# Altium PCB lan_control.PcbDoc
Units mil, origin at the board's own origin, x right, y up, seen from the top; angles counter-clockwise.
Board outline 3947.03 x 3354.83 mil, 2 copper layers (Top Layer, Bottom Layer); 54 components, 48 nets, 205 pads, 217 vias.
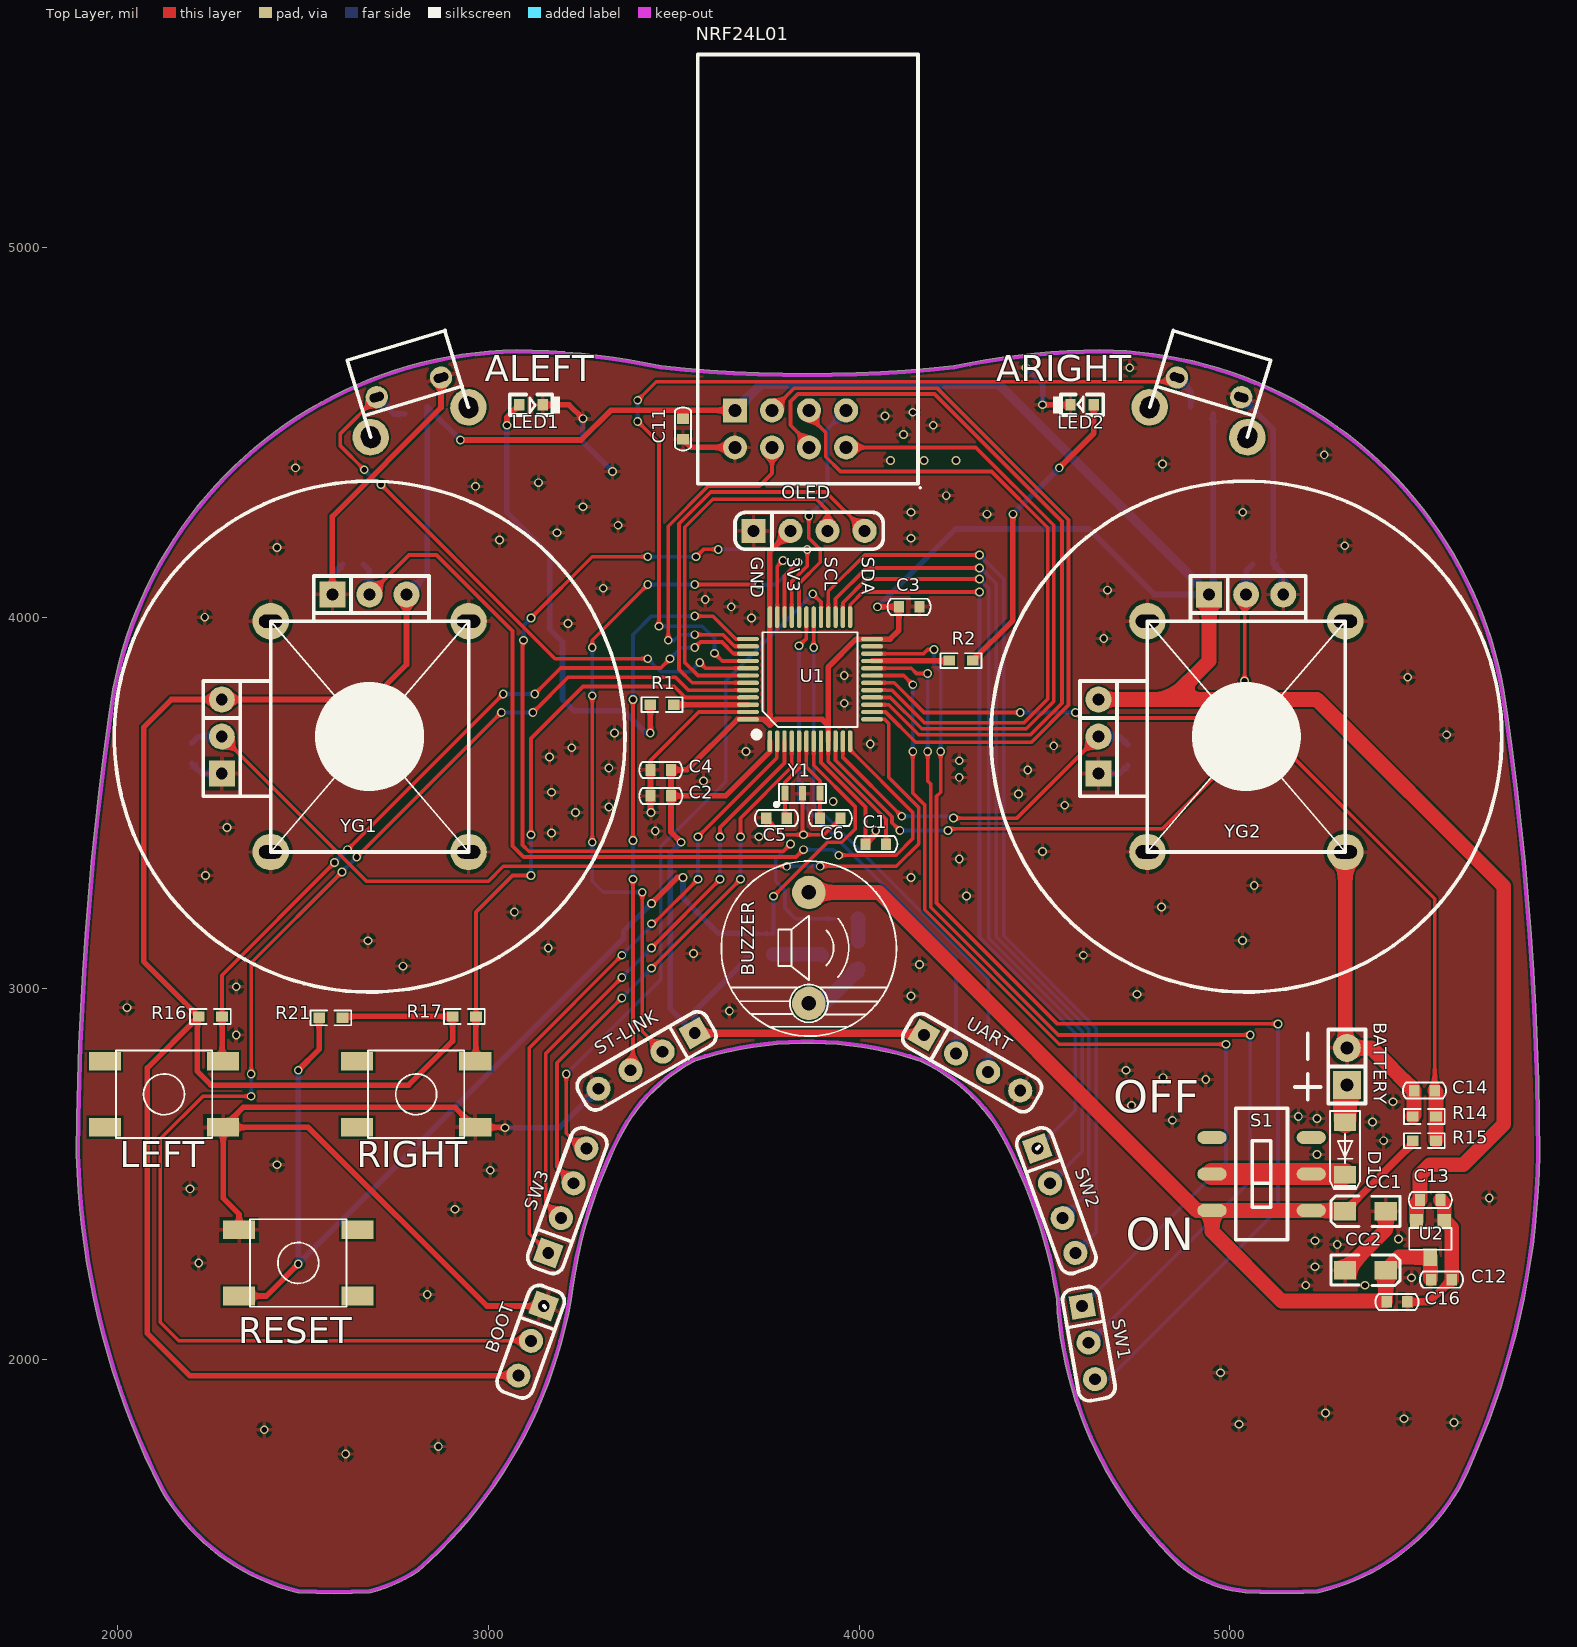
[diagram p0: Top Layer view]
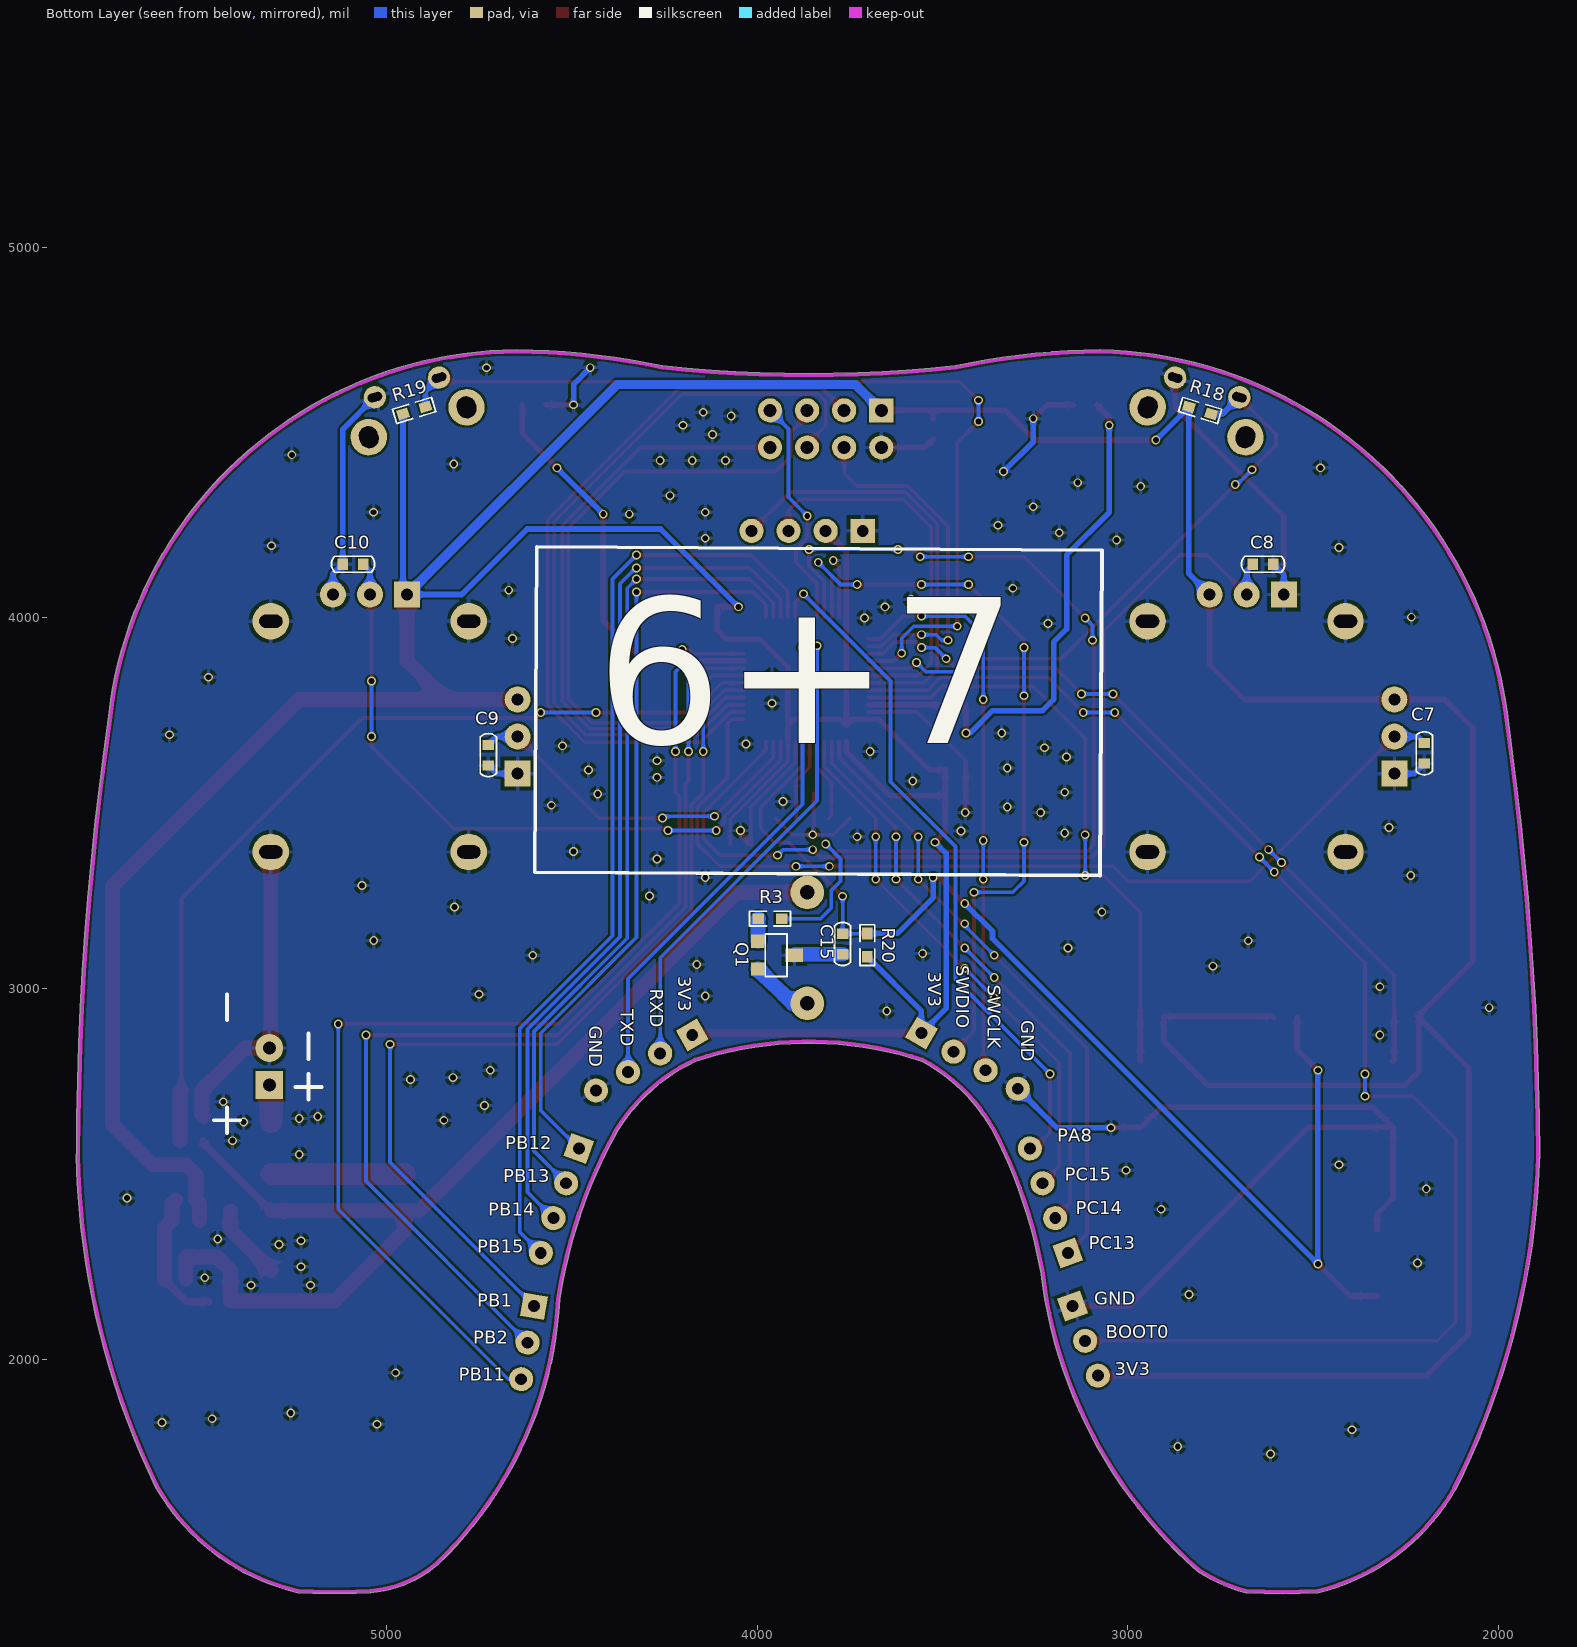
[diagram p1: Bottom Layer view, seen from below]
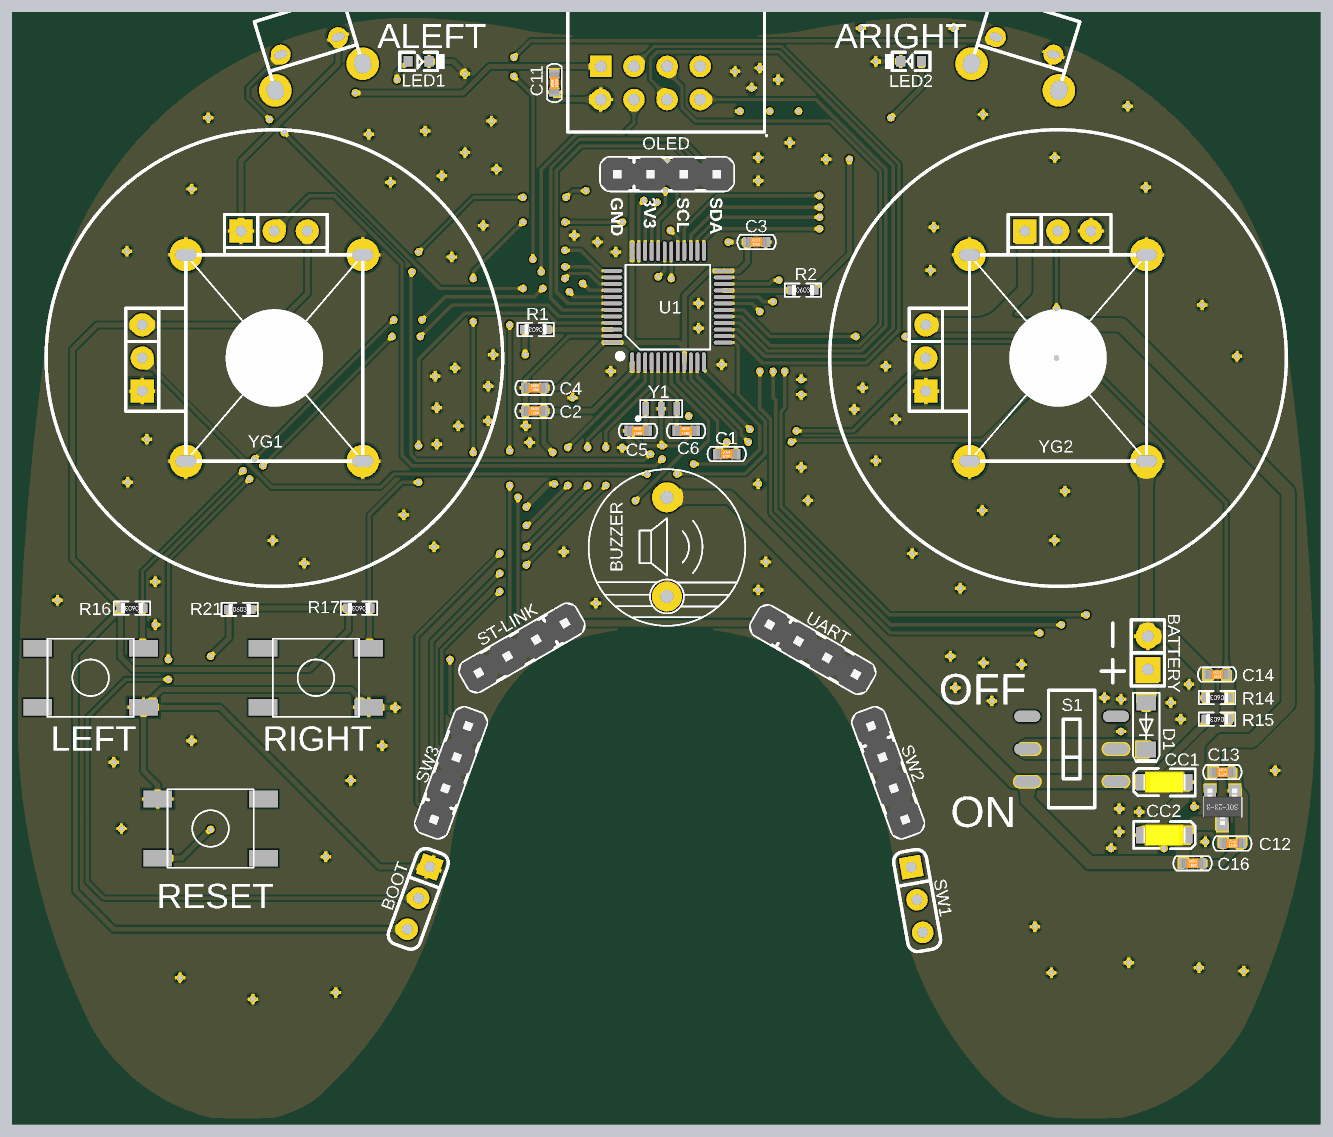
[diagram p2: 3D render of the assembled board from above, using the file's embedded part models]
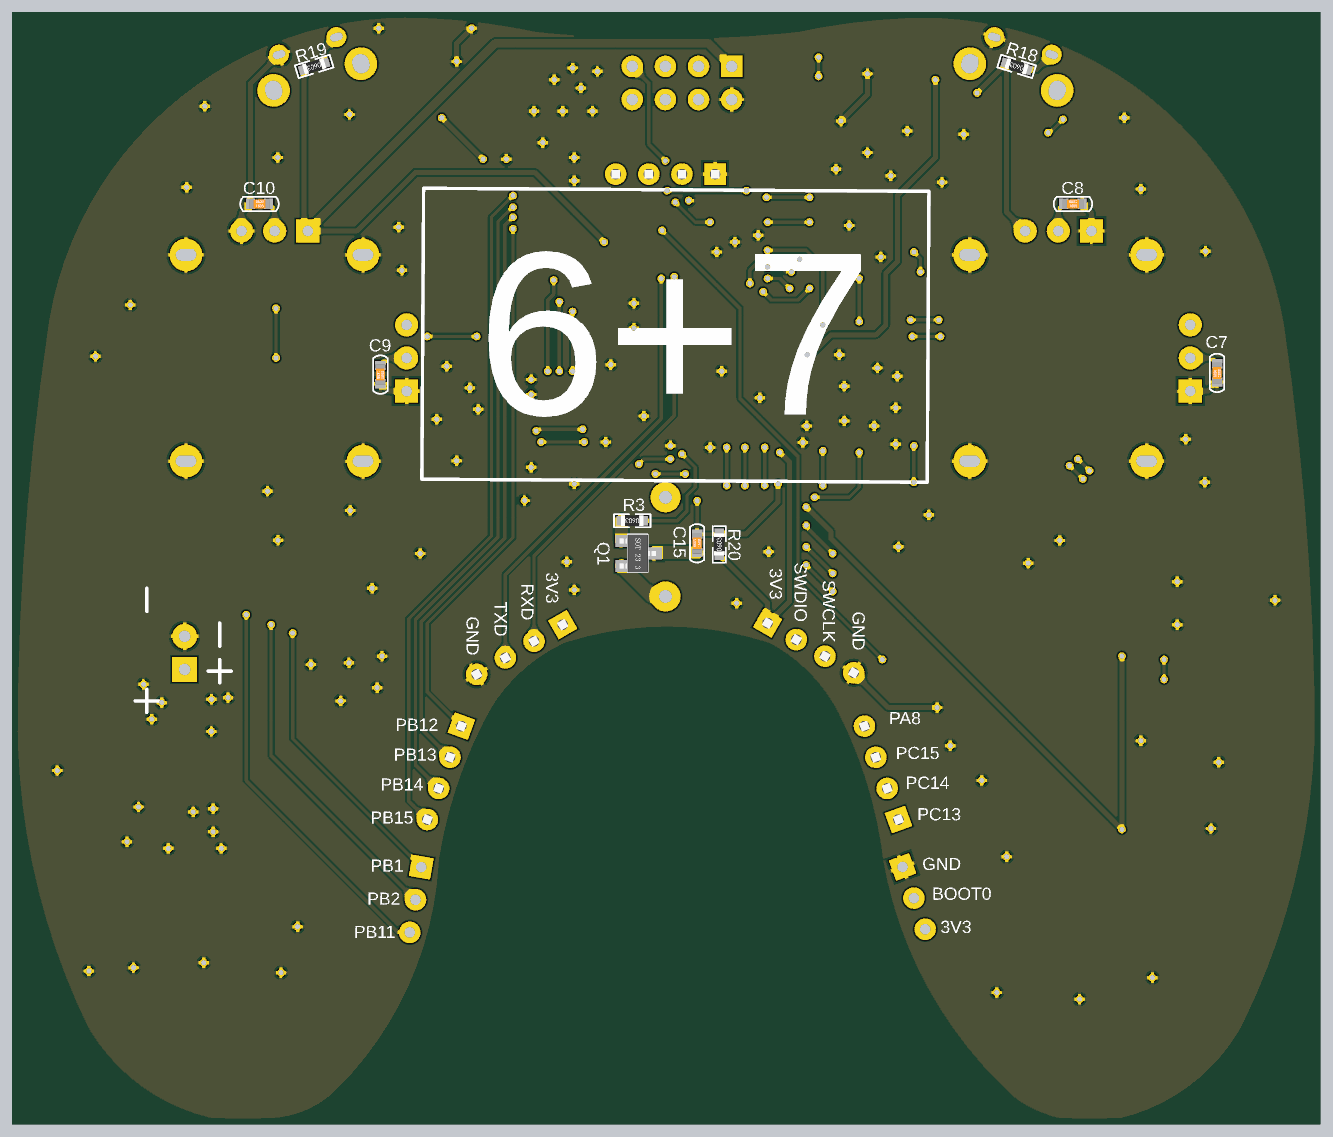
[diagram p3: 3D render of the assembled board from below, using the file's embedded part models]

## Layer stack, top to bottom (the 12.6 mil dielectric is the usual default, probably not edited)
Top Solder: solder mask 0.4, Solder Resist, Dk 3.5
Top Layer: signal copper 1.4
Dielectric 1: dielectric 12.6, FR-4, Dk 4.8
Bottom Layer: signal copper 1.4
Bottom Solder: solder mask 0.4, Solder Resist, Dk 3.5

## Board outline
2486.67,1370.8 ccw(c2487.17,1375.79) 2486.93,1370.78 ccw(c2583.63,3341.93) 2680.33,1370.78 ccw(c2680.08,1375.79) 2680.44,1370.78 ccw(c2680.08,1375.79) 2681.3,1370.92 ccw(c2587.07,1760.86) 2812.02,1428.7 ccw(c2587.07,1760.86) 2812.05,1428.72 2812.02,1428.7 ccw(c2809.24,1432.87) 2812.55,1429.11 ccw(c1973.33,2381.46) 3223.63,2162.32 ccw(c3218.69,2163.19) 3223.67,2162.58 cw(c4538.77,2003.24) 3357.01,2601.84 ccw(c3352.55,2604.13) 3357.01,2601.84 cw(c4538.77,2003.24) 3357.02,2601.87 ccw(c3352.55,2604.13) 3357.02,2601.87 cw(c3782.54,2383.23) 3555.42,2804.29 cw(c3860.42,1873.76) 4165.51,2804.26 cw(c3952.67,2353.1) 4375.79,2617.33 cw(c3176.19,1949.24) 4532.59,2162.67 ccw(c5594.98,2216.85) 4860.9,1446.96 ccw(c4864.36,1450.59) 4861.08,1446.8 ccw(c5067.76,1685.5) 5042.18,1370.79 5042.34,1370.78 ccw(c5140.12,3341.87) 5237.91,1370.78 ccw(c5237.66,1375.79) 5238.21,1370.8 ccw(c5237.66,1375.79) 5238.81,1370.91 ccw(c5105.6,1951.38) 5621.76,1654.26 ccw(c5617.41,1656.76) 5621.92,1654.57 ccw(c3705.18,2585.84) 5835.92,2552.78 ccw(c5830.91,2552.86) 5835.92,2552.86 ccw(c5830.91,2552.86) 5835.91,2553.22 ccw(c-2681.94,2522.43) 5749.27,3734.6 ccw(c4643.92,3611) 4649.84,4723.23 ccw(c4649.81,4718.22) 4649.81,4723.23 ccw(c4649.81,4718.22) 4649.77,4723.23 ccw(c4664.52,2756.14) 4255.32,4680.26 cw(c3859.14,8433.86) 3465.79,4679.96 ccw(c3053.83,2745.84) 3075.06,4723.23 ccw(c3075.01,4718.22) 3075.01,4723.23 ccw(c3075.01,4718.22) 3074.92,4723.23 ccw(c3094.76,3595.59) 1975.55,3734.67 ccw(c3094.76,3595.59) 1975.54,3734.58 1975.55,3734.67 ccw(c10675.5,2502.64) 1888.89,2552.89 ccw(c1893.91,2552.86) 1888.9,2552.76 ccw(c1893.91,2552.86) 1888.9,2552.73 ccw(c4019.2,2607.34) 2115.78,1649.12 ccw(c2120.26,1651.38) 2115.91,1648.88 ccw(c2624.96,1941.26) 2485.94,1370.92 ccw(c2624.96,1941.26) 2485.99,1370.91 2485.94,1370.92 ccw(c2487.17,1375.79)

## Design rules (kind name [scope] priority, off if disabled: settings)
Clearance [All] p1: gap=6 ignorepadtopadclearanceinfootprint=FALSE
PolygonConnect [All] p1: connectstyle=Relief reliefconductorwidth=10 reliefentries=4 polygonreliefangle="90 Angle" airgapwidth=10
RoutingVias [All] p1: holewidth=28 width=50 viastyle="Through Hole" minholewidth=28 minwidth=50 maxholewidth=28 maxwidth=50
SolderMaskExpansion [All] p1: expansion=4
Width [All] p1: maxlimit=200 minlimit=10 preferedwidth=40 toplayer_prefwidth=20 minimp=50.000000 maximp=50.000000 favimp=50.000000
30 further rules are at their usual default settings.

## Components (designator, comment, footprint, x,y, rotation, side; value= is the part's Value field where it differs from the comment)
ALEFT "左肩键" FWAL 2800,4575 r197 top
ARIGHT "右肩键" FWAL 4930,4575 r163 top
BATTERY "DC4.2V" SIP2 5315.86,2740 r90 top
BOOT "CON3" SIP3 3149.06,2143.78 r250 top
BUZZER "Bell" 蜂鸣器BUZZER-D12 3865,3110 r0 top
C1 "100NF" C_0603 4045,3390 r180 top
C2 "100NF" C_0603 3465,3520 r0 top
C3 "100NF" C_0603 4135,4030 r180 top
C4 "100NF" C_0603 3465,3590 r0 top
C5 "22PF" C_0603 3777.34,3460 r180 top
C6 "22PF" C_0603 3922.34,3460 r180 top
C7 "100NF" C_0603 2200,3635 r270 bottom
C8 "100NF" C_0603 2635,4145 r180 bottom
C9 "100NF" C_0603 4725,3630 r270 bottom
C10 "100NF" C_0603 5090,4145 r180 bottom
C11 "100NF" C_0603 3525,4510 r270 top
C12 "100NF" C_0603 5570.86,2215 r0 top
C13 "100NF" C_0603 5540.86,2430 r0 top
C14 "100NF" C_0603 5525,2725 r0 top
C15 "100NF" C_0603 3769.23,3120.68 r90 bottom
C16 "100NF" C_0603 5450.86,2155 r0 top
CC1 "10uF" C_1206 5365.86,2400 r0 top
CC2 "10uF" C_1206 5365.86,2240 r180 top
D1 "IN4007" SOD-123 5310.86,2640 r270 top
LED1 "R_LED" LED0603 3115,4575 r270 top
LED2 "B_LED" LED0603 4601.5,4575 r90 top
LEFT "左键" KEYSW-6X6 2125,2715 r180 top
NRF24L01 "HEADER 4X2" 24L01 3815,4510 r270 top
OLED "OLED" SIP4 3715.23,4234.93 r0 top
Q1 "2TY" SOT23-213 3948.32,3090 r270 bottom
R1 "103" R0603 3468.26,3765.94 r180 top value=1K
R2 "103" R0603 4275,3885 r0 top value=1K
R3 "103" R0603 3965,3188.76 r0 bottom value=10K
R14 "103" R0603 5525,2655 r180 top value=10K
R15 "103" R0603 5525,2590 r180 top value=10K
R16 "103" R0603 2250,2925 r180 top value=10K
R17 "103" R0603 2935,2925 r180 top value=10K
R18 "103" R0603 2805,4560 r17 bottom value=10K
R19 "103" R0603 4925,4560 r343 bottom value=10K
R20 "103" R0603 3702.58,3117.5 r90 bottom value=10K
R21 "103" R0603 2575,2921.5 r0 top value=10K
RESET "RESET键" KEYSW-6X6 2487.17,2260 r0 top
RIGHT "右键" KEYSW-6X6 2805,2715 r180 top
S1 "MSS22D18" MSS22D18 5085.86,2500 r90 top
ST-LINK "ST-LINK" SIP4 3556.37,2879.95 r210 top
SW1 "CON3" SIP3 4601.77,2143.25 r280 top
SW2 "CON4" SIP4 4480.81,2568.73 r290 top
SW3 "CON4" SIP4 3161.74,2287.25 r70 top
U1 "STM32F103C8T6_LQFP48" LQFP48_STM32 3759.41,3667.52 r90 top
U2 "XC6206" SOT23-PIN132 5540.86,2325 r180 top
UART "UART" SIP4 4175,2875 r330 top
Y1 "8MHZ" Y3213 3847.34,3526.87 r0 top
YG1 "5K" GY 2680,3680 r0 top
YG2 "5K" GY 5045,3680 r0 top

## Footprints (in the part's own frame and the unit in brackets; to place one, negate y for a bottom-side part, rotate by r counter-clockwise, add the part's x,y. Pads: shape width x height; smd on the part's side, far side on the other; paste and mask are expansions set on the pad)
24L01 [mil]
  round 65 hole 35: 1(50,-150) 3(50,-50) 4(-50,-50) 5(50,50) 6(-50,50) 7(50,150) 8(-50,150)
  rect 65x65 hole 35: 2(-50,-150)
  silkscreen extent -1010,-250 159,350
C_0603 [mm]
  rect 0.7x0.8 smd: 1(-0.703,0) 2(0.703,0)
  silkscreen extent -1.48,-0.55 1.48,0.55, body extent -0.8,-0.4 0.8,0.4, height 0.8
C_1206 [mil]
  rect 60x50 smd: 1(-55,0) 2(55,0)
  silkscreen extent -93,-42 93,41, body extent -63,-31 63,31, height 63
FWAL [mm]
  round 2.5 hole 1.3 slot 1.5 at 90 deg: 1(3.5,1.25) 2(-3.5,1.25)
  round 1.524 hole 0.6 slot 1 at 0 deg: 3(2.3,-1.25) 4(-2.3,-1.25)
  silkscreen extent -3.5,-4.25 3.5,1.25
GY [mil]
  rect 70x70 hole 32: 1(-399.12,-100) 4(-100.85,383.25)
  round 70 hole 32: 2(-399.12,0) 3(-399.12,100) 5(-0.85,383.25) 6(99.15,383.25)
  round 98.43 hole 35.43 slot 62.99 at 0 deg: 7(-267.31,311.21) 8(266.69,311.21) 9(266.69,-311.21) 10(-267.31,-311.21)
  silkscreen extent -689,-689 689,689
KEYSW-6X6 [mm]
  rect 2.2x1.27 smd: 1(-4.051,-2.263) 2(-4.051,2.263) 3(4.051,-2.263) 4(4.051,2.263)
  silkscreen extent -3.3,-3 3.3,3
LED0603 [mm]
  rect 0.8x0.7 smd: 1(0,-0.8) 2(0,0.8)
  silkscreen extent -0.7,-1.45 0.7,1.99
LQFP48_STM32 [mm]
  oval 1.5x0.3 smd: 1(0,0) 2(0,-0.5) 3(0,-1) 4(0,-1.5) 5(0,-2) 6(0,-2.5) 7(0,-3) 8(0,-3.5) 9(0,-4) 10(0,-4.5) 11(0,-5) 12(0,-5.5) 25(8.5,-5.5) 26(8.5,-5) 27(8.5,-4.5) 28(8.5,-4) 29(8.5,-3.5) 30(8.5,-3) 31(8.5,-2.5) 32(8.5,-2) 33(8.5,-1.5) 34(8.5,-1) 35(8.5,-0.5) 36(8.5,0)
  oval 0.3x1.5 smd: 13(1.5,-7) 14(2,-7) 15(2.5,-7) 16(3,-7) 17(3.5,-7) 18(4,-7) 19(4.5,-7) 20(5,-7) 21(5.5,-7) 22(6,-7) 23(6.5,-7) 24(7,-7) 37(7,1.5) 38(6.5,1.5) 39(6,1.5) 40(5.5,1.5) 41(5,1.5) 42(4.5,1.5) 43(4,1.5) 44(3.5,1.5) 45(3,1.5) 46(2.5,1.5) 47(2,1.5) 48(1.5,1.5)
  silkscreen extent 0.3,-5.99 7.47,1.07
MSS22D18 [mm]
  oval 0.889x2 smd: 1(-2.5,-3.4) 2(0,-3.4) 3(2.5,-3.4) 4(2.5,3.4) 5(0,3.4) 6(-2.5,3.4)
  silkscreen extent -4.5,-1.77 4.5,1.77, body extent -4.44,-1.78 4.44,1.78, height 3
R0603 [mm]
  rect 0.8x0.7 smd: 1(-0.8,0) 2(0.8,0)
  silkscreen extent -1.4,-0.51 1.4,0.51, body extent -0.85,-0.41 0.85,0.39, height 0.56
SIP2 [mil]
  rect 75x75 hole 35: 1(0,0)
  round 75 hole 35: 2(100,0)
  silkscreen extent -50,-50 150,50
SIP3 [mil]
  rect 65x65 hole 32: 1(-0.23,0.07)
  round 65 hole 32: 2(99.77,0.07) 3(199.77,0.07)
  silkscreen extent -50,-50 255,50, body extent -50,-50 250,50, height 10
SIP4 [mil]
  rect 65x65 hole 32: 1(-0.23,0.07)
  round 65 hole 32: 2(99.77,0.07) 3(199.77,0.07) 4(299.77,0.07)
  silkscreen extent -50,-50 350,50, body extent -50,-50 350,50, height 336
SOD-123 [mm]
  rect 1.2x1.5 smd: 1(0,0) 2(3.6,0)
  silkscreen extent -0.76,-1.02 4.57,1.02
SOT23-213 [mil]
  rect 36x47.24 smd: 1(-0.36,48.99)
  rect 36x36 smd: 2(-37.86,-49.43) 3(37.14,-49.43)
  silkscreen extent -57,-30 57,29, body extent -57,-55 57,55, height 47
SOT23-PIN132 [mil]
  rect 36x36 smd: 1(-37.86,-49.43) 2(37.14,-49.43)
  rect 36x47.24 smd: 3(-0.36,48.99)
  silkscreen extent -57,-30 57,29, body extent -57,-55 57,55, height 47
Y3213 [mm]
  rect 0.5x1 smd: 1(-1.2,0) 2(0,0) 3(1.2,0)
  silkscreen extent -1.9,-0.89 1.6,0.65, body extent -1.52,-0.64 1.52,0.64, height 0.8
蜂鸣器BUZZER-D12 [mm]
  round 2.3 hole 1: 1(-0.013,3.8) 2(-0.013,-3.8)
  silkscreen extent -6.01,-6.05 5.99,5.95

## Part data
ALEFT ARIGHT: library part SW-PB
BATTERY: library part CON2, "Connector"
BUZZER: "Electrical Bell"
C1 C2 C3 C4 C5 C6 C7 C8 C9 C10 C11 C12 C13 C14 C15 C16: library part CAP, "Capacitor"
CC1 CC2: library part "CAPACITOR POL", "Capacitor"
D1: library part DIODE, "Diode"
LED1 LED2: library part LED
LEFT RESET RIGHT: library part SW
OLED ST-LINK UART: library part CON4, "Connector"
Q1: library part PNP, "PNP Bipolar Transistor"
R1 R2 R3 R14 R15 R16 R17 R18 R19 R20 R21: library part Res2, "Resistor"
S1: library part SW2X3
SW2 SW3: "Connector"
U1: library part STM32_LQFP48
U2: library part LM317, "3-Terminal Adjustable Positive Voltage Regulator"
Y1: library part Y
YG1 YG2: library part YG

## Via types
v1: diameter 23.62, hole 15.75, Top Layer to Bottom Layer, 217 vias

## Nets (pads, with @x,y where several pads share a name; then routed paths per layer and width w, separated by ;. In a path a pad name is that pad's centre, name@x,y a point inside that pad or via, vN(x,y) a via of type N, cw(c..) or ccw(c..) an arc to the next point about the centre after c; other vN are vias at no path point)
3V3: BOOT.3 C1.1 C2.2 C3.2 C4.2 C11.1 C13.1 NRF24L01.2 OLED.2 R16.2 R17.2 R18.2 R19.2 R20.1 R21.2 ST-LINK.1 U1.1 U1.9 U1.24 U1.36 U1.48 U2.2 UART.1 YG1.3 YG1.6 YG2.3 YG2.4 | length 16193.5
  Top Layer w10: U1.9 3916.89,3613.02 4072.67,3457.24 C1.1 ; UART.1@4170.01,2880 UART.1
  Top Layer w15: R21.2 2610,2925 R17.2 2903.5,2858.5 2785,2740 2251.73,2740 2215,2776.73 R16.2@2215,2921.5 ; YG1.6 2779.15,3874.15 2685,3780 YG1.3 2145,3780 2070,3705 2070,3073.5 R16.2 R16.2@2215,2921.5 ; v1(2924.33,4480) 3250,4480 3330,4560 3535,4560 ; BOOT.3 2193.97,1956.03 2080,2070 2080,2786.5 R16.2@2215,2921.5 ; v1(3520,3395) 3492.67,3422.33 C2.2 ; C11.1 3525,4550 3535,4560 ; NRF24L01.2 3535,4560 ; U1.1 3759.41,3639.41 3640,3520 C2.2 ; OLED.2 3759.41,4179.41 U1.36 3759.41,3710 ; 3916.61,3710.38 3900.41,3726.57 3775.98,3726.57 3759.41,3710 ; U1.9 3916.89,3867.58 3992.14,3942.83 4034.72,3942.83 U1.24 4083.5,3943.11 4107.33,3966.94 C3.2 v1(4050,4030) ; C2.2 C4.2 3535,3590 3671.57,3726.57 U1.48 3742.83,3726.57 3759.41,3710
  Top Layer w20: ST-LINK.1 UART.1@4170.01,2880
  Top Layer w40: YG2.3 4840,3780 ; YG2.4 4944.15,3884.15 4840,3780 ; U2.2 5503.71,2420.53 C13.1 5513.19,2498.27 5539.92,2525 5630,2525 5739.25,2634.25 5739.25,3276.07 5235.31,3780 4840,3780
  Bottom Layer w15: YG1.6 2835.12,4119.23 R18.2 v1(2924.33,4480) ; v1(3520,3395) 3490,3365 3490,2946.6 ST-LINK.1 3556.6,2940.03 R20.1 ; v1(4050,4030) 4260,4240 4620,4240 4796.75,4063.25 YG2.4 4955.12,4074.23 R19.2
  Bottom Layer w25: NRF24L01.2 3735,4630 4377.4,4630 YG2.4
ADC0: C10.2 U1.10 YG2.5 | length 1837.7
  Top Layer w10: U1.10 3936.57,3615.97 4088.67,3463.87 4088.67,3447.89 v1(4110,3426.56) ; v1(4240,3426.56) 4245,3431.56 4818.26,3431.56 5040,3653.29 v1(5040,3680) ; v1(5040,3830) 5040,4059.11 YG2.5
  Bottom Layer w10: v1(4110,3426.56) v1(4240,3426.56) ; v1(5040,3680) v1(5040,3830)
  Bottom Layer w15: YG2.5 5044.15,4126.82 C10.2
ADC1: C9.1 U1.11 YG2.2 | length 980.6
  Top Layer w10: U1.11 3956.26,3623.74 v1(4115,3465) ; v1(4255,3460.09) 4425.96,3460.09 YG2.2
  Bottom Layer w10: v1(4115,3465) 4250.09,3465 v1(4255,3460.09)
  Bottom Layer w15: YG2.2 4702.67,3680 C9.1
ADC2: C8.1 U1.12 YG1.5 | length 2641.7
  Top Layer w10: YG1.5 2785.89,4170 2860,4170 3065,3965 3065,3385 3095,3355 3830,3355 v1(3850,3375) ; v1(3945,3360) 4100,3360 4145,3405 4145,3475.39 3975.94,3644.45 U1.12
  Bottom Layer w10: v1(3850,3375) 3930,3375 v1(3945,3360)
  Bottom Layer w15: C8.1 2679.15,4128.52 YG1.5
ADC3: C7.1 U1.13 YG1.2 | length 2579.1
  Top Layer w10: YG1.2 2670.88,3290 3000,3290 3040,3330 v1(3805,3330) ; v1(3895,3330) 4100.39,3330 4161,3390.61 4161,3489 4080,3570 4080,3715 4068.43,3726.57 U1.13
  Bottom Layer w10: v1(3805,3330) v1(3895,3330)
  Bottom Layer w15: C7.1 2217.33,3680 YG1.2
ALEFT_KEY: ALEFT.3 R18.1 U1.41 | length 1635.9
  Top Layer w10: v1(2665,4400) 2600,4465 2600,4496.57 ALEFT.3 ; v1(2710,4360) 3180,3890 v1(3430,3890) ; v1(3570,3880) 3585.63,3864.37 U1.41
  Bottom Layer w10: v1(2665,4400) 2705,4360 v1(2710,4360) ; v1(3430,3890) 3465,3855 3545,3855 v1(3570,3880)
  Bottom Layer w15: ALEFT.3 2743.81,4550.79 R18.1
ARIGHT_KEY: ARIGHT.3 R19.1 U1.40 | length 2511.1
  Top Layer w10: v1(3402.67,4530) 3460,4472.67 v1(3460,3977.81) ; v1(3402.67,4587.33) 3452.83,4637.49 4846.75,4637.49 ARIGHT.3 ; v1(3610,3905) 3630.95,3884.05 U1.40
  Bottom Layer w10: v1(3402.67,4530) v1(3402.67,4587.33) ; v1(3460,3977.81) 3577.19,3977.81 3610,3945 v1(3610,3905)
  Bottom Layer w15: ARIGHT.3 4894.88,4611.45 R19.1
B_LED: R2.1 U1.21 | length 208.9
  Top Layer w15: U1.21 4242.56,3884.05 R2.1
BAT_DET: C14.2 R14.1 R15.1 U1.18 | length 2412.9
  Top Layer w10: U1.18 4095,3825 4175,3745 v1(4434.65,3745) ; v1(4583.4,3745) 4598.4,3730 5065,3730 5552.67,3242.33 C14.2
  Top Layer w40: C14.2 5556.5,2721.17 R14.1 R15.1
  Bottom Layer w10: v1(4434.65,3745) v1(4583.4,3745)
BOOT0: BOOT.2 U1.44 | length 3842
  Top Layer w10: v1(2360,2710) 2230,2710 2115,2595 2115,2100 2165,2050 BOOT.2 ; v1(2360,2770) 2360,3070 v1(2605,3315) ; v1(2645,3355) v1(3035,3745) ; v1(3120,3745) 3215,3840 3505,3840 3539.68,3805.32 U1.44
  Bottom Layer w10: v1(2360,2710) v1(2360,2770) ; v1(2605,3315) v1(2645,3355) ; v1(3035,3745) v1(3120,3745)
BUZZER: R3.1 U1.33 | length 2725.8
  Top Layer w10: v1(3095,3940) 3092.19,3937.19 3092.19,3387.81 3109,3371 3796,3371 v1(3815,3390) ; v1(3115,4000) 3280,4165 v1(3430,4165) ; v1(3560,4165) 3580,4185 v1(3620,4185) ; U1.33 3818.46,4098.46 3860,4140 v1(3860,4185)
  Bottom Layer w10: v1(3095,3940) 3095,3980 v1(3115,4000) ; v1(3430,4165) v1(3560,4165) ; v1(3620,4185) v1(3860,4185) ; v1(3815,3390) 3775,3350 3775,3290 3800,3265 3800,3217.5 3828.74,3188.76 R3.1
CE: NRF24L01.3 U1.38 | length 951.2
  Top Layer w10: v1(3485,3940) 3485,4247.63 3593.37,4356 3731,4356 3765,4390 NRF24L01.3 ; v1(3556.6,3955) 3632.63,3955 3664.2,3923.43 U1.38
  Bottom Layer w10: v1(3485,3940) 3501.57,3940 3516.57,3955 v1(3556.6,3955)
CSN: NRF24L01.4 U1.14 | length 2077
  Top Layer w10: NRF24L01.4 3825,4620 4210,4620 4565,4265 4565,3765 4465,3665 4152.63,3665 4071.37,3746.26 U1.14
GND: ALEFT.4 ARIGHT.4 BATTERY.2 BOOT.1 C1.2 C2.1 C3.1 C4.1 C5.2 C6.1 C7.2 C8.2 C9.2 C10.1 C11.2 C12.2 C13.2 C14.1 C15.1 C16.2 CC1.2 CC2.2 LED1.2 LED2.2 LEFT.2 NRF24L01.1 OLED.1 Q1.1 R14.2 RESET.2 RIGHT.2 ST-LINK.4 U1.8 U1.23 U1.35 U1.47 U2.1 UART.4 Y1.2 YG1.1 YG1.4 YG1.7 YG1.8 YG1.9 YG1.10 YG2.1 YG2.6 YG2.7 YG2.8 YG2.9 YG2.10 | length 7550.3
  Top Layer w10: C4.1 3437.33,3615.83 3567.76,3746.26 U1.47 ; C5.2 3794.67,3415 v1(3849.84,3415) ; U1.35 3779.09,4139.42 v1(3794.67,4155) ; Y1.2 3847.34,3417.5 v1(3849.84,3415) ; U1.8 3897.2,3610 4017.33,3489.87 C1.2 ; C6.1 3905.01,3415 v1(3849.84,3415)
  Top Layer w15: RESET.2 2327.68,2391.8 2284.49,2435 LEFT.2 ; YG1.4 2579.15,4274.15 2872.21,4567.21 ALEFT.4 ; v1(3045,2625) 3044.1,2625.9 RIGHT.2 2910.38,2680 2338.59,2680 LEFT.2 ; LED1.2 3217.67,4575 v1(3255,4537.67) ; BOOT.1 2996.03,2143.97 2514.1,2625.9 LEFT.2 ; C4.1 C2.1 3437.33,3476.17 v1(3438.5,3475) ; C11.2 3547.33,4460 NRF24L01.1 ; OLED.1 OLED.1@3717.67,4232.33 ; C1.2 4045,3417.67 v1(4045,3426.56) ; v1(4495,4575) LED2.2
  Top Layer w20: C16.2 5538.52,2155 C12.2
  Top Layer w40: CC2.2 5420.86,2350 CC1.2 ; YG2.9 5311.69,2844.17 BATTERY.2 5382.33,2840 C14.1 5497.33,2658.83 R14.2 ; C13.2 5578.71,2419.81 U2.1 5598.52,2354.62 C12.2
  Bottom Layer w15: C7.2 2227.33,3580 YG1.1 ; YG1.4 2579.15,4116.82 C8.2 ; v1(3045,2625) 3191.8,2625 ST-LINK.4 ; v1(3255,4537.67) 3255,4475 v1(3335,4395) ; v1(4450,4675.3) 4495,4630.3 v1(4495,4575) ; YG2.1 4702.67,3580 C9.2 ; ARIGHT.4 5117.67,4508.9 C10.1 5144.15,4118.52 YG2.6
  Bottom Layer w40: C15.1 3896.67,3093.01 Q1.1
  other v1: 2615,1745 2865,1765 2395.2,1810 5025,1825 5605,1830 5470,1840 5258.18,1855 4975,1963.78 2835,2175 5205,2200 5365,2200 5490,2220 5230,2250 2218.5,2260 5290,2310 5230,2320 5455,2325 2910,2405 5700,2435 2195,2460 3005,2510 2430,2525 5235,2552.86 5415,2590 5385,2640 4845,2645 5235,2650 5185,2655 4735,2685 5440,2695 4935,2755 4820,2760 4720,2780 2320,2875.17 3650,2940 2025,2948.83 4140,2980 4750,2985 2320,3005 2770,3060.79 4162.67,3065 4605,3090 3553.33,3095 3161.6,3110 2675,3129.26 5033.95,3130 3070,3206.5 4816.1,3220 4290,3250 5065.86,3278.15 4140,3300 2236.82,3305 4270,3350 4495,3370 3730,3410 3170,3420 3450,3425 2295,3435 3235,3475 3325,3490 4555,3495 3930,3505 4430,3525 3170,3530 3580,3560 4270,3570 4455,3590 3325,3595 4270,3615 3165,3625 3695,3640 3225,3650 4525,3655 4030,3660 5585,3685 3340,3690 3960,3770 5480,3840 3960,3845 4660,3944.68 3215,3985 3710,4000 2235,4002.17 3655,4030 3585,4050 4670,4075 3310,4080 2430,4190 5310,4195 3030,4210 4140,4215 3185,4230 3350,4250 4345,4280 4140,4285 5035,4285 3255,4300 4235,4330 2965,4355 3135,4365 2480,4405 4818.26,4415 4085,4425 4175,4425 4261.44,4425 5255,4440 4120,4495 4200,4520 4070,4545 4145,4555 4730,4675
IRQ: NRF24L01.8 U1.32 | length 635.6
  Top Layer w10: U1.32 3838.15,4093.15 3895,4150 3895,4185 3864.5,4215.5 v1(3864.5,4275)
  Bottom Layer w10: v1(3864.5,4275) 3915,4325.5 3915,4510 NRF24L01.8
LEFT_KEY: LEFT.1 R16.1 U1.39 | length 2037.6
  Top Layer w10: R16.1 2281.5,3036.5 v1(2585,3340) ; v1(2620,3375) v1(3040,3795) ; v1(3125,3795) 3195,3865 3465,3865 v1(3490,3890) ; v1(3556.6,3920) 3571.6,3935 3630,3935 3661.26,3903.74 U1.39
  Top Layer w15: R16.1 2281.5,2807.09 LEFT.1
  Bottom Layer w10: v1(2585,3340) v1(2620,3375) ; v1(3040,3795) v1(3125,3795) ; v1(3490,3890) 3520,3920 v1(3556.6,3920)
MISO: NRF24L01.7 U1.16 | length 1677.7
  Top Layer w10: NRF24L01.7 4315,4460 4525,4250 4525,3775 4451,3701 4169,3701 4084.37,3785.63 U1.16
MOSI: NRF24L01.6 U1.17 | length 1821.1
  Top Layer w10: NRF24L01.6 3865,4545 3910,4500 3910,4435 3950,4395 4357.37,4395 4509,4243.37 4509,3781.63 4444.37,3717 4177,3717 4088.68,3805.32 U1.17
NetBATTERY_1: BATTERY.1 D1.1 | length 102.1
  Top Layer w40: BATTERY.1@5310.86,2735 BATTERY.1
  Top Layer w60: D1.1 BATTERY.1@5310.86,2735
NetBUZZER_2: BUZZER.2 Q1.3 | length 171.5
  Bottom Layer w40: BUZZER.2 3905.29,2960.39 Q1.3
NetD1_2: D1.2 S1.2 S1.5 | length 359.6
  Top Layer w40: D1.2@5309.12,2500 D1.2
  Top Layer w60: S1.5 S1.2 D1.2@5309.12,2500
NetLED1_1: LED1.1 R1.2 | length 1221
  Top Layer w15: v1(3050,4520) 3050,4541.5 LED1.1 ; v1(3436.76,3690) R1.2
  Bottom Layer w15: v1(3050,4520) 3050,4285 3165,4170 3165,3970 3200,3935 3200,3780 3230,3750 3365,3750 3425,3690 v1(3436.76,3690)
NetLED2_1: LED2.1 R2.2 | length 825.2
  Top Layer w15: R2.2 4415,3993.5 v1(4415,4280) ; v1(4540,4405) 4632.99,4497.99 LED2.1
  Bottom Layer w15: v1(4415,4280) v1(4540,4405)
NetQ1_2: Q1.2 R3.2 | length 61.4
  Bottom Layer w40: R3.2 3997.75,3187.5 Q1.2
OSC_IN: C5.1 U1.5 Y1.1 | length 225.3
  Top Layer w10: C5.1 3800.09,3464.91 Y1.1 3800.09,3556.95 3838.15,3595 U1.5
OSC_OUT: C6.2 U1.6 Y1.3 | length 223.1
  Top Layer w10: U1.6 3857.83,3597.17 3895,3560 3895,3527.28 Y1.3 3894.58,3460.09 C6.2
PA8: SW3.4 U1.29 | length 1873.7
  Top Layer w10: v1(3210,2770) 3210,2610 SW3.4@3251.03,2568.97 ; v1(3875,4065) 3897.2,4042.8 U1.29
  Bottom Layer w10: v1(3210,2770) 3465,3025 3465,3383.43 3640,3558.43 3640,3830 v1(3875,4065) ; SW3.4@3251.03,2568.97 SW3.4
PB1: SW1.1 U1.19 | length 2571.2
  Top Layer w10: U1.19 4120.32,3844.68 v1(4145,3820) ; v1(4145,3640) 4145,3527.63 4177,3495.63 4177,3213 4540,2850 v1(4990,2850)
  Bottom Layer w10: v1(4145,3640) v1(4145,3820) ; SW1.1 4990,2531.68 v1(4990,2850)
PB2: SW1.2 U1.20 | length 2805
  Top Layer w10: U1.20 4140.63,3864.37 4155,3850 v1(4185,3850) ; v1(4185,3640) 4185,3560 4193,3552 4193,3219.63 4537.46,2875.17 v1(5055,2875.17)
  Bottom Layer w10: v1(4185,3640) v1(4185,3850) ; SW1.2 5055,2480.84 v1(5055,2875.17)
PB11: SW1.3 U1.22 | length 3107.2
  Top Layer w10: U1.22 4173.74,3903.74 4185,3915 v1(4202.11,3915) ; v1(4220,3640) 4220,3530 4209,3519 4209,3231 4535,2905 v1(5130,2905)
  Bottom Layer w10: v1(4202.11,3915) 4202.11,3872.89 4220,3855 v1(4220,3640) ; SW1.3 4671.52,1946.52 5130,2405 v1(5130,2905)
PB12: SW2.1 U1.25 | length 2047.5
  Top Layer w10: U1.25 3975.94,4035.94 4010,4070 v1(4325,4070)
  Bottom Layer w10: v1(4325,4070) 4325,3138.4 4583.4,2880 4583.4,2671.58 SW2.1
PB13: SW2.2 U1.26 | length 2214.8
  Top Layer w10: U1.26 3956.26,4041.26 4020,4105 v1(4325,4105)
  Bottom Layer w10: v1(4325,4105) 4350,4080 4350,3136.03 4601.8,2884.23 4601.8,2561.8 SW2.2
PB14: SW2.3 U1.27 | length 2378.5
  Top Layer w10: U1.27 3936.57,4051.57 4020,4135 v1(4325,4135)
  Bottom Layer w10: v1(4325,4135) 4327.26,4135 4370,4092.26 4370,3140 4619.16,2890.84 4619.16,2450.99 SW2.3
PB15: SW2.4 U1.28 | length 2555.3
  Top Layer w10: U1.28 3916.89,4071.89 4015,4170 v1(4325,4170)
  Bottom Layer w10: v1(4325,4170) 4390,4105 4390,3142.63 4640,2892.63 4640,2343.66 SW2.4
PC13: SW3.1 U1.2 | length 1710.5
  Top Layer w10: SW3.1 3110,2338.66 3110,2840 v1(3360,3090) ; v1(3440,3175) 3445,3175 v1(3565.32,3295.32) ; v1(3565.32,3410) 3777.91,3622.59 3777.91,3666.34 U1.2 U1.2@3779.09,3639.41
  Bottom Layer w10: v1(3360,3090) 3440,3170 v1(3440,3175) ; v1@3565,3295 v1(3565.32,3295.32) v1(3565.32,3410)
PC14: SW3.2 U1.3 | length 1570.1
  Top Layer w10: SW3.2 3155,2421.83 3155,2825 v1(3360,3030) ; v1(3440,3110) v1(3625,3295) ; v1(3625,3410) 3625,3435 3798.78,3608.78 U1.3
  Bottom Layer w10: v1(3360,3030) v1(3440,3110) ; v1(3625,3295) v1(3625,3410)
PC15: SW3.3 U1.4 | length 1473.5
  Top Layer w10: SW3.3 3185,2520 3185,2800 v1(3360,2975) ; v1(3440,3055) v1(3680,3295) ; v1(3680,3410) 3680,3460 3818.46,3598.46 U1.4
  Bottom Layer w10: v1(3360,2975) v1(3440,3055) ; v1(3680,3295) v1(3680,3410)
R_LED: R1.1 U1.46 | length 200.6
  Top Layer w15: R1.1 U1.46
RIGHT_KEY: R17.1 RIGHT.1 U1.45 | length 1618
  Top Layer w10: R17.1 2966.5,3206.5 3065,3305 v1(3115,3305) ; v1(3115,3415) 3115,3675 3255,3815 3501.5,3815 3530.87,3785.63 U1.45
  Top Layer w15: RIGHT.1 2966.5,2806.11 R17.1
  Bottom Layer w10: v1(3115,3305) v1(3115,3415)
RST: C15.2 R20.2 R21.1 RESET.1 U1.7 | length 3383.4
  Top Layer w10: v1(3769.23,3249.23) 3915,3395 3953.44,3395 3990,3431.56 3990,3490 3877.52,3602.48 U1.7
  Top Layer w15: RESET.1 2400.9,2170.9 v1(2487.17,2257.17) ; v1(2487.17,2780) 2543.5,2836.33 R21.1 ; v1(3440,3230) 3510,3300 v1(3525,3300)
  Bottom Layer w10: R20.2 3703.22,3148.35 C15.2 v1(3769.23,3249.23)
  Bottom Layer w15: v1(2487.17,2780) v1(2487.17,2257.17) 3365,3135 3365,3155 v1(3440,3230) ; v1(3525,3300) 3525,3245 3621,3149 R20.2
RXD: U1.31 UART.2 | length 1360.5
  Top Layer w10: v1(3838.15,3925) 3857.83,3944.68 U1.31
  Bottom Layer w10: v1(3838.15,3925) 3838.15,3506.85 4261.44,3083.56 UART.2
SCK: NRF24L01.5 U1.15 | length 2099
  Top Layer w10: NRF24L01.5 3865,4470 3815,4520 3815,4584 3835,4604 4203.37,4604 4547.37,4260 4547.37,3770 4462.37,3685 4161,3685 4080.05,3765.95 U1.15
SCL: OLED.3 U1.42 | length 1033.5
  Top Layer w10: U1.42 3565.32,3844.68 3530,3880 3530,4245 3605,4320 3885,4320 3915,4290 OLED.3
SDA: OLED.4 U1.43 | length 1174.4
  Top Layer w10: U1.43 3550,3825 3514,3861 3514,4254 3600,4340 3910,4340 OLED.4
SWCLK: ST-LINK.3 U1.37 | length 1534.4
  Top Layer w10: ST-LINK.3 3390,2786.6 v1(3390,3295) ; v1(3390,3400) v1(3390,3780) ; v1(3556.6,4005) 3605.25,4005 3667.14,3943.11 U1.37
  Bottom Layer w10: v1(3390,3295) v1(3390,3400) ; v1(3390,3780) 3390,3955 3440,4005 v1(3556.6,4005)
SWDIO: ST-LINK.2 U1.34 | length 2055
  Top Layer w10: v1(3280,3395) v1(3280,3790) ; v1(3280,3920) 3280,3940 v1(3430,4090) ; v1(3415,3260) 3415,2885 ST-LINK.2 ; v1(3556.6,4090) v1(3730,4090) ; U1.34 3798.78,4113.78 v1(3835,4150)
  Bottom Layer w10: v1(3280,3395) 3280,3290 3310,3260 v1(3415,3260) ; v1(3280,3790) v1(3280,3920) ; v1(3430,4090) v1(3556.6,4090) ; v1(3730,4090) 3775,4090 v1(3835,4150)
TXD: U1.30 UART.3 | length 1421.9
  Top Layer w10: v1(3877.52,3920) U1.30
  Bottom Layer w10: v1(3877.52,3920) 3877.52,3497.48 4348.04,3026.96 UART.3
VBAT: BUZZER.1 C12.1 C16.1 CC1.1 CC2.1 R15.2 S1.1 S1.6 U2.3 | length 2954.2
  Top Layer w20: CC1.1@5309.28,2401.57 CC1.1 5493.5,2582.65 R15.2 ; 5381.52,2157.19 5381.66,2157.33 ; C16.1@5420.86,2157.33 C16.1 ; C12.1@5541.21,2216.97 C12.1
  Top Layer w40: BUZZER.1 4053.08,3259.61 4911.12,2401.57 S1.6 ; CC1.1@5309.28,2401.57 S1.1 S1.6 ; 5381.52,2157.19 5140.14,2157.19 4952,2345.33 S1.6 ; 5381.66,2157.33 5420.86,2157.33 CC2.1 5456.86,2276.01 U2.3 C12.1@5541.21,2216.97
pads on no net: ALEFT.1 ALEFT.2 ARIGHT.1 ARIGHT.2 LEFT.3 LEFT.4 RESET.3 RESET.4 RIGHT.3 RIGHT.4 S1.3 S1.4

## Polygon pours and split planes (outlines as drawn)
GND on Bottom Layer "GND_L02_P013" (solid, remove dead copper, pour order 13): 2486.67,1370.8 ccw(c2487.17,1375.79) 2486.93,1370.78 ccw(c2583.63,3341.92) 2680.33,1370.78 ccw(c2680.08,1375.79) 2680.44,1370.78 ccw(c2680.08,1375.79) 2681.3,1370.92 ccw(c2587.07,1760.86) 2812.02,1428.7 ccw(c2586.3,1761.24) 2812.05,1428.72 2812.02,1428.7 ccw(c2809.24,1432.87) 2812.55,1429.11 ccw(c1973.33,2381.46) 3223.63,2162.32 ccw(c3218.69,2163.19) 3223.67,2162.58 cw(c4538.77,2003.24) 3357.01,2601.84 ccw(c3352.47,2604.11) 3357.01,2601.84 cw(c4539.16,2005.85) 3357.02,2601.87 ccw(c3352.67,2604.21) 3357.02,2601.87 cw(c3782.54,2383.23) 3555.42,2804.29 cw(c3860.42,1873.76) 4165.51,2804.26 cw(c3952.67,2353.1) 4375.79,2617.33 cw(c3176.19,1949.24) 4532.59,2162.67 ccw(c5594.98,2216.85) 4860.9,1446.96 ccw(c4864.36,1450.59) 4861.08,1446.8 ccw(c5067.76,1685.5) 5042.18,1370.79 5042.34,1370.78 ccw(c5140.12,3341.87) 5237.91,1370.78 ccw(c5237.66,1375.79) 5238.21,1370.8 ccw(c5237.66,1375.79) 5238.81,1370.91 ccw(c5105.6,1951.38) 5621.76,1654.26 ccw(c5617.41,1656.76) 5621.92,1654.57 ccw(c3705.18,2585.84) 5835.92,2552.78 ccw(c5830.91,2552.86) 5835.92,2552.86 ccw(c5830.91,2552.86) 5835.91,2553.22 ccw(c-2681.94,2522.43) 5749.27,3734.6 ccw(c4643.92,3611) 4649.84,4723.23 ccw(c4649.81,4718.22) 4649.81,4723.23 ccw(c4649.81,4718.22) 4649.77,4723.23 ccw(c4664.52,2756.13) 4255.32,4680.26 cw(c3859.14,8433.86) 3465.79,4679.96 ccw(c3053.83,2745.84) 3075.06,4723.23 ccw(c3075.01,4718.22) 3075.01,4723.23 ccw(c3075.01,4718.22) 3074.92,4723.23 ccw(c3094.76,3595.59) 1975.55,3734.67 ccw(c3094.74,3595.85) 1975.54,3734.58 1975.55,3734.67 ccw(c10675.5,2502.64) 1888.89,2552.89 ccw(c1893.91,2552.86) 1888.9,2552.76 ccw(c1893.9,2552.84) 1888.9,2552.73 ccw(c4019.2,2607.34) 2115.78,1649.12 ccw(c2120.26,1651.38) 2115.91,1648.88 ccw(c2624.96,1941.26) 2485.94,1370.92 ccw(c2624.72,1942.19) 2485.99,1370.91 2485.94,1370.92 ccw(c2487.17,1375.79)
GND on Top Layer "GND_L01_P014" (solid, remove dead copper, pour order 14): 2486.67,1370.8 ccw(c2487.17,1375.79) 2486.93,1370.78 ccw(c2583.63,3341.92) 2680.33,1370.78 ccw(c2680.08,1375.79) 2680.44,1370.78 ccw(c2680.08,1375.79) 2681.3,1370.92 ccw(c2587.07,1760.86) 2812.02,1428.7 ccw(c2586.3,1761.24) 2812.05,1428.72 2812.02,1428.7 ccw(c2809.24,1432.87) 2812.55,1429.11 ccw(c1973.33,2381.46) 3223.63,2162.32 ccw(c3218.69,2163.19) 3223.67,2162.58 cw(c4538.77,2003.24) 3357.01,2601.84 ccw(c3352.47,2604.11) 3357.01,2601.84 cw(c4539.16,2005.85) 3357.02,2601.87 ccw(c3352.67,2604.21) 3357.02,2601.87 cw(c3782.54,2383.23) 3555.42,2804.29 cw(c3860.42,1873.76) 4165.51,2804.26 cw(c3952.67,2353.1) 4375.79,2617.33 cw(c3176.19,1949.24) 4532.59,2162.67 ccw(c5594.98,2216.85) 4860.9,1446.96 ccw(c4864.36,1450.59) 4861.08,1446.8 ccw(c5067.76,1685.5) 5042.18,1370.79 5042.34,1370.78 ccw(c5140.12,3341.87) 5237.91,1370.78 ccw(c5237.66,1375.79) 5238.21,1370.8 ccw(c5237.66,1375.79) 5238.81,1370.91 ccw(c5105.6,1951.38) 5621.76,1654.26 ccw(c5617.41,1656.76) 5621.92,1654.57 ccw(c3705.18,2585.84) 5835.92,2552.78 ccw(c5830.91,2552.86) 5835.92,2552.86 ccw(c5830.91,2552.86) 5835.91,2553.22 ccw(c-2681.94,2522.43) 5749.27,3734.6 ccw(c4643.92,3611) 4649.84,4723.23 ccw(c4649.81,4718.22) 4649.81,4723.23 ccw(c4649.81,4718.22) 4649.77,4723.23 ccw(c4664.52,2756.13) 4255.32,4680.26 cw(c3859.14,8433.86) 3465.79,4679.96 ccw(c3053.83,2745.84) 3075.06,4723.23 ccw(c3075.01,4718.22) 3075.01,4723.23 ccw(c3075.01,4718.22) 3074.92,4723.23 ccw(c3094.76,3595.59) 1975.55,3734.67 ccw(c3094.74,3595.85) 1975.54,3734.58 1975.55,3734.67 ccw(c10675.5,2502.64) 1888.89,2552.89 ccw(c1893.91,2552.86) 1888.9,2552.76 ccw(c1893.9,2552.84) 1888.9,2552.73 ccw(c4019.2,2607.34) 2115.78,1649.12 ccw(c2120.26,1651.38) 2115.91,1648.88 ccw(c2624.96,1941.26) 2485.94,1370.92 ccw(c2624.72,1942.19) 2485.99,1370.91 2485.94,1370.92 ccw(c2487.17,1375.79)

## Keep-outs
Keep-Out Layer:
  lines w10: 3551.8,2808.37 cw(c3860.42,1873.76) 4169.04,2808.37 ; 3553.33,2808.86 ccw(c3782.54,2383.23) 3352.55,2604.13 ccw(c4538.77,2003.24) 3218.69,2163.19 cw(c1973.33,2381.46) 2809.24,1432.87 cw(c2587.07,1760.86) 2680.08,1375.79 cw(c2583.63,3341.93) 2487.17,1375.79 cw(c2624.96,1941.26) 2120.26,1651.38 cw(c4019.2,2607.34) 1893.91,2552.86 cw(c10675.5,2502.64) 1980.52,3733.97 cw(c3094.76,3595.59) 3075.01,4718.22 cw(c3053.83,2745.84) 3465,4675 ccw(c3859.14,8433.86) 4256.11,4675.3 cw(c4664.52,2756.14) 4649.81,4718.22 cw(c4643.92,3611) 5744.3,3733.97 cw(c-2681.94,2522.43) 5830.9,2552.86 cw(c3705.18,2585.84) 5617.41,1656.76 cw(c5105.6,1951.38) 5237.66,1375.79 cw(c5140.12,3341.87) 5042.59,1375.79 cw(c5067.76,1685.5) 4864.36,1450.59 cw(c5594.98,2216.85) 4537.59,2163.19 ccw(c3176.19,1949.24) 4380.11,2619.88 ccw(c3952.67,2353.1) 4167.51,2808.86

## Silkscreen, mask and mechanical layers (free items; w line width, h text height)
Top Overlay:
  lines w10: 3150.23,2145 3149.2,2143.97 3153.17,2140 ; 4479.77,2568.97 4485.8,2575 ; 5175,2735 5245,2735 ; 5210,2700 5210,2770 ; 5210,2810 5210,2880 ; 2682.61,4487.65 2682.61,4487.65
  text "GND" at 3695.14,4165 h60 r270
  text "3V3" at 3794.67,4165 h60 r270
  text "SCL" at 3895,4165 h60 r270
  text "SDA" at 3995,4165 h60 r270
  text "OFF" at 4685,2635 h150
  text "ON" at 4720,2265 h150
Bottom Overlay:
  lines w10: 5175,2735 5245,2735 ; 5210,2700 5210,2770 ; 5210,2810 5210,2880 ; 5395,2645 5465,2645 ; 5430,2610 5430,2680 ; 5430,2915 5430,2985 ; 3069.65,4182.97 4594.68,4192.27 4600.03,3314.3 3075,3305 3069.65,4182.97
  text "6+7" at 4434.65,3510 h800
  text "SWDIO" at 3475,3062.5 h60 r90
  text "3V3" at 3550,3045 h60 r90
  text "3V3" at 4225,3033.27 h60 r90
  text "SWCLK" at 3390,3010 h60 r90
  text "RXD" at 4300,3000 h60 r90
  text "TXD" at 4380.11,2945 h60 r90
  text "GND" at 3300,2915 h60 r90
  text "GND" at 4465,2900 h60 r90
  text "PA8" at 3190,2575 h60
  text "PB12" at 4680,2555 h60
  text "PC15" at 3170,2470 h60
  text "PB13" at 4685,2465 h60
  text "PC14" at 3140,2380 h60
  text "PB14" at 4725,2375 h60
  text "PC13" at 3105,2285 h60
  text "PB15" at 4755,2275 h60
  text "GND" at 3090,2135 h60
  text "PB1" at 4755,2130 h60
  text "BOOT0" at 3060,2045 h60
  text "PB2" at 4765,2030 h60
  text "3V3" at 3035,1945 h60
  text "PB11" at 4805,1930 h60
